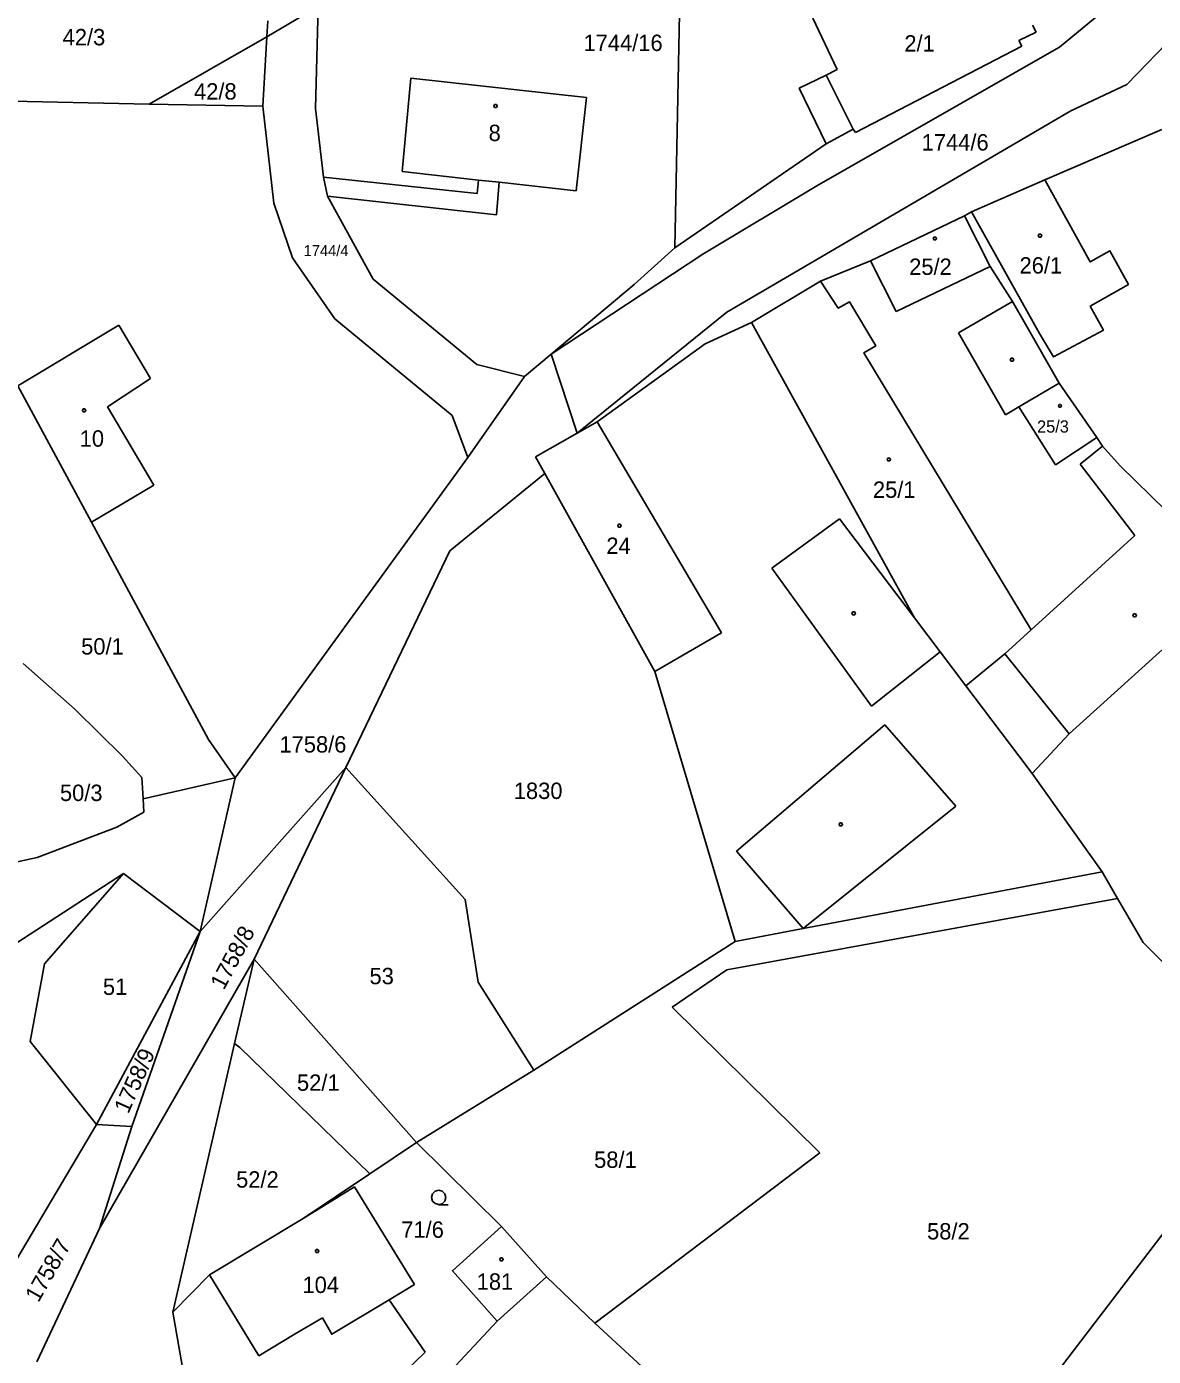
# Model space of a CAD drawing. Extents: x -799786 to -795190, y -1021716 to -1017834.
# Drawn here: x -798047.9 to -797930.9, y -1019191.9 to -1019053.9 of the extents above; entities that cross this region are included whole.
import ezdxf

# ---------------------------------------------------------------- set-up
doc = ezdxf.new("R2010")
doc.units = 0
for name, color, linetype in [('Default', 7, 'Continuous'), ('KN_HRANICE', 7, 'Continuous'), ('KN_KULTURY', 7, 'Continuous'), ('KN_PARCELY', 7, 'Continuous'), ('KN_SLUCKY', 7, 'Continuous')]:
    doc.layers.add(name, color=color, linetype=linetype)

# ---------------------------------------------------------------- blocks, each defined once
blk = doc.blocks.new('304')
at = {"layer": 'Default'}
blk.add_lwpolyline([(0, 0), (-0.38, 0.1), (-0.65, 0.37), (-0.75, 0.74), (-0.65, 1.11), (-0.38, 1.38), (-0.01, 1.48), (0.36, 1.38), (0.63, 1.11), (0.73, 0.73), (0.63, 0.35), (0.36, 0.08), (-0.02, -0.02), (0.98, -0.02)], dxfattribs=at)
blk = doc.blocks.new('NAHRADNI_SYMBOL')
at = {"layer": 'Default'}
blk.add_lwpolyline([(0.09, 0.15), (0.18, 0), (0.09, -0.15), (-0.09, -0.15), (-0.18, 0), (-0.09, 0.15), (0.09, 0.15)], dxfattribs=at)
blk = doc.blocks.new('402')
at = {"layer": 'Default'}
blk.add_lwpolyline([(0.09, 0.15), (0.18, 0), (0.09, -0.15), (-0.09, -0.15), (-0.18, 0), (-0.09, 0.15), (0.09, 0.15)], dxfattribs=at)

msp = doc.modelspace()

# ---------------------------------------------------------------- linework, layer by layer
at = {"layer": 'KN_HRANICE'}
for p, q in [((-797979.99, -1019047.61), (-797980.56, -1019076.83)), ((-797934.54, -1019050.94), (-797940.64, -1019055.99)), ((-798022.92, -1019054.93), (-798017.6, -1019051.79)), ((-798017.6, -1019051.79), (-798017.86, -1019062.37)), ((-797966.24, -1019053), (-797963.7, -1019058.32)), ((-798022.83, -1019053.26), (-798022.92, -1019054.93)), ((-797944.84, -1019055.3), (-797943.07, -1019054.43)), ((-797943.44, -1019053.71), (-797943.07, -1019054.43)), ((-798035.14, -1019061.9), (-798022.92, -1019054.93)), ((-798022.92, -1019054.93), (-798023.33, -1019062.14)), ((-797944.53, -1019055.88), (-797944.84, -1019055.3)), ((-797933.64, -1019059.89), (-797928.48, -1019054.53)), ((-797940.64, -1019055.99), (-797965.65, -1019070.29)), ((-797961.81, -1019064.86), (-797944.53, -1019055.88)), ((-797964.86, -1019058.91), (-797963.7, -1019058.32)), ((-798008.89, -1019068.91), (-798007.98, -1019059.22)), ((-798007.98, -1019059.22), (-797989.73, -1019061.24)), ((-797967.67, -1019060.26), (-797964.86, -1019058.91)), ((-797939.47, -1019062.61), (-797933.64, -1019059.89)), ((-797989.73, -1019061.24), (-797990.8, -1019070.91)), ((-797964.85, -1019066.02), (-797967.67, -1019060.26)), ((-798035.14, -1019061.9), (-798051.33, -1019061.57)), ((-798023.33, -1019062.14), (-798035.14, -1019061.9)), ((-798023.33, -1019062.14), (-798022.2, -1019072.21)), ((-798017.86, -1019062.37), (-798017.06, -1019069.5)), ((-797975.16, -1019083.51), (-797939.47, -1019062.61)), ((-797964.85, -1019066.02), (-797962.04, -1019064.5)), ((-797962.04, -1019064.5), (-797961.81, -1019064.86)), ((-797942.17, -1019069.78), (-797930, -1019064.56)), ((-797980.56, -1019076.83), (-797964.85, -1019066.02)), ((-798017.06, -1019069.5), (-798016.63, -1019071.48)), ((-798001.09, -1019071.18), (-798017.06, -1019069.5)), ((-798000.94, -1019069.79), (-798008.89, -1019068.91)), ((-798000.94, -1019069.79), (-798001.09, -1019071.18)), ((-797998.8, -1019070.03), (-797999.09, -1019073.4)), ((-797990.8, -1019070.91), (-797998.8, -1019070.03)), ((-797965.65, -1019070.29), (-797977.66, -1019077.48)), ((-797949.77, -1019073.09), (-797942.17, -1019069.78)), ((-798022.2, -1019072.21), (-798020.28, -1019077.86)), ((-798016.63, -1019071.48), (-798011.89, -1019080.08)), ((-798016.63, -1019071.48), (-797999.09, -1019073.4)), ((-797960.26, -1019078.18), (-797950.51, -1019073.52)), ((-797950.51, -1019073.52), (-797949.77, -1019073.09)), ((-797947.83, -1019078.78), (-797950.51, -1019073.52)), ((-798020.28, -1019077.86), (-798015.86, -1019084.19)), ((-797977.66, -1019077.48), (-797993.4, -1019087.85)), ((-797984.78, -1019080.65), (-797980.56, -1019076.83)), ((-797965.46, -1019080.28), (-797960.26, -1019078.18)), ((-797957.58, -1019083.44), (-797960.26, -1019078.18)), ((-797957.58, -1019083.44), (-797947.83, -1019078.78)), ((-797947.83, -1019078.78), (-797945.52, -1019082.39)), ((-798011.89, -1019080.08), (-798001.14, -1019088.93)), ((-797993.4, -1019087.85), (-797984.78, -1019080.65)), ((-797972.6, -1019084.58), (-797965.46, -1019080.28)), ((-797945.52, -1019082.39), (-797944.16, -1019084.77)), ((-798015.86, -1019084.19), (-798003.7, -1019094.22)), ((-797975.16, -1019083.51), (-797990.71, -1019096.07)), ((-797977.41, -1019086.81), (-797972.6, -1019084.58)), ((-797972.6, -1019084.58), (-797955.69, -1019115.25)), ((-797944.16, -1019084.77), (-797940.66, -1019090.89)), ((-797988.62, -1019094.88), (-797977.41, -1019086.81)), ((-798001.14, -1019088.93), (-797996.19, -1019090.18)), ((-797996.19, -1019090.18), (-797993.4, -1019087.85)), ((-797993.4, -1019087.85), (-797990.71, -1019096.07)), ((-798002.07, -1019098.6), (-797996.19, -1019090.18)), ((-798041.14, -1019105.32), (-798048.79, -1019091.15)), ((-797944.86, -1019093.34), (-797940.66, -1019090.89)), ((-797940.66, -1019090.89), (-797936.77, -1019096.53)), ((-798003.7, -1019094.22), (-798002.07, -1019098.6)), ((-797944.86, -1019093.34), (-797941.05, -1019099.35)), ((-797990.71, -1019096.07), (-797988.62, -1019094.88)), ((-797995.05, -1019098.54), (-797990.71, -1019096.07)), ((-797941.05, -1019099.35), (-797936.77, -1019096.53)), ((-797936.77, -1019096.53), (-797936.16, -1019097.42)), ((-798002.07, -1019098.6), (-798026.22, -1019131.83)), ((-797995.05, -1019098.54), (-797994.08, -1019100.27)), ((-797936.16, -1019097.42), (-797934.34, -1019099.45)), ((-797934.34, -1019099.45), (-797929.59, -1019104.1)), ((-797994.08, -1019100.27), (-798003.92, -1019108.28)), ((-797994.08, -1019100.27), (-797982.65, -1019120.79)), ((-798028.98, -1019127.85), (-798041.14, -1019105.32)), ((-798003.92, -1019108.28), (-798014.72, -1019130.78)), ((-797939.64, -1019127.27), (-797922.11, -1019111.42)), ((-797953.02, -1019118.78), (-797955.69, -1019115.25)), ((-797950.37, -1019122.28), (-797953.02, -1019118.78)), ((-798048.24, -1019119.97), (-798042.83, -1019124.75)), ((-797982.65, -1019120.79), (-797974.31, -1019148.84)), ((-797944.86, -1019129.55), (-797950.37, -1019122.28)), ((-798042.83, -1019124.75), (-798037.9, -1019129.58)), ((-797943.46, -1019131.4), (-797939.64, -1019127.27)), ((-798026.22, -1019131.83), (-798028.98, -1019127.85)), ((-798037.9, -1019129.58), (-798035.91, -1019131.81)), ((-797943.46, -1019131.4), (-797944.86, -1019129.55)), ((-798014.72, -1019130.78), (-798029.85, -1019147.81)), ((-798014.72, -1019130.78), (-798024.25, -1019150.65)), ((-798002.35, -1019144.46), (-798014.72, -1019130.78)), ((-797943.46, -1019131.4), (-797936.21, -1019141.61)), ((-798035.91, -1019131.81), (-798035.77, -1019134.03)), ((-798035.77, -1019134.03), (-798026.22, -1019131.83)), ((-798026.22, -1019131.83), (-798029.85, -1019147.81)), ((-798035.77, -1019134.03), (-798035.69, -1019135.42)), ((-798035.69, -1019135.42), (-798038.5, -1019136.97)), ((-798038.5, -1019136.97), (-798046.79, -1019140.13)), ((-798046.79, -1019140.13), (-798049.66, -1019140.75)), ((-798037.82, -1019141.78), (-798057.09, -1019154.27)), ((-798037.82, -1019141.78), (-798046, -1019151.14)), ((-798029.85, -1019147.81), (-798037.82, -1019141.78)), ((-797961.9, -1019146.49), (-797936.21, -1019141.61)), ((-797936.21, -1019141.61), (-797934.6, -1019144.37)), ((-798000.98, -1019153.06), (-798002.35, -1019144.46)), ((-797975.17, -1019151.78), (-797934.6, -1019144.37)), ((-797934.6, -1019144.37), (-797931.93, -1019148.94)), ((-797967.24, -1019147.5), (-797961.9, -1019146.49)), ((-798040.62, -1019167.84), (-798029.85, -1019147.81)), ((-798029.85, -1019147.81), (-798036.96, -1019168.05)), ((-797974.31, -1019148.84), (-797967.24, -1019147.5)), ((-797995.22, -1019162.2), (-797974.31, -1019148.84)), ((-797931.93, -1019148.94), (-797917.67, -1019163.19)), ((-798040.29, -1019178.61), (-798024.25, -1019150.65)), ((-798024.25, -1019150.65), (-798026.27, -1019159.43)), ((-798024.25, -1019150.65), (-798007.38, -1019169.71)), ((-798046, -1019151.14), (-798047.51, -1019159.22)), ((-797980.83, -1019155.66), (-797975.17, -1019151.78)), ((-798000.98, -1019153.06), (-797995.22, -1019162.2)), ((-797965.53, -1019170.76), (-797980.83, -1019155.66)), ((-798047.51, -1019159.22), (-798040.62, -1019167.84)), ((-798026.27, -1019159.43), (-798032.69, -1019187.31)), ((-798025.74, -1019159.83), (-798026.27, -1019159.43)), ((-798012.22, -1019172.95), (-798025.74, -1019159.83)), ((-798007.38, -1019169.71), (-797995.22, -1019162.2)), ((-797958.45, -1019216.47), (-797917.67, -1019163.19)), ((-798053.76, -1019189.97), (-798040.62, -1019167.84)), ((-798040.62, -1019167.84), (-798036.96, -1019168.05)), ((-798036.96, -1019168.05), (-798040.29, -1019178.61)), ((-798012.22, -1019172.95), (-798007.38, -1019169.71)), ((-797998.56, -1019178.4), (-798007.38, -1019169.71)), ((-797988.89, -1019188.44), (-797965.53, -1019170.76)), ((-798019.17, -1019177.58), (-798012.22, -1019172.95)), ((-798019.17, -1019177.58), (-798013.83, -1019174.29)), ((-798013.83, -1019174.29), (-798007.6, -1019184.43)), ((-798046.82, -1019192.47), (-798040.29, -1019178.61)), ((-798028.89, -1019183.42), (-798019.17, -1019177.58)), ((-797993.89, -1019183.63), (-797998.56, -1019178.4)), ((-798028.89, -1019183.42), (-798032.69, -1019187.31)), ((-797993.89, -1019183.63), (-797999, -1019188.24)), ((-797988.89, -1019188.44), (-797993.89, -1019183.63)), ((-798010.23, -1019186.02), (-798007.6, -1019184.43)), ((-798006.49, -1019191.45), (-798010.23, -1019186.02)), ((-798032.69, -1019187.31), (-798030.99, -1019196.93)), ((-797999, -1019188.24), (-798004.3, -1019193.91)), ((-797958.45, -1019216.47), (-797988.89, -1019188.44)), ((-798008.6, -1019193.51), (-798006.49, -1019191.45))]:
    msp.add_line(p, q, dxfattribs=at)
msp.add_lwpolyline([(-797998.56, -1019178.4), (-798003.67, -1019183.01), (-797999, -1019188.24)], dxfattribs=at)
at = {"layer": 'KN_SLUCKY'}
for p, q in [((-797964.86, -1019058.91), (-797962.04, -1019064.5)), ((-797998.8, -1019070.03), (-798000.94, -1019069.79)), ((-797945.52, -1019082.39), (-797951.1, -1019085.66)), ((-798048.79, -1019091.15), (-798038.3, -1019084.86)), ((-798038.3, -1019084.86), (-798035.02, -1019090.4)), ((-797951.1, -1019085.66), (-797946.24, -1019094.15)), ((-798035.02, -1019090.4), (-798039.46, -1019093.32)), ((-798039.46, -1019093.32), (-798034.65, -1019101.48)), ((-797946.24, -1019094.15), (-797944.86, -1019093.34)), ((-797988.62, -1019094.88), (-797975.73, -1019116.8)), ((-797936.16, -1019097.42), (-797938.48, -1019099.3)), ((-797938.48, -1019099.3), (-797932.82, -1019106.7)), ((-798034.65, -1019101.48), (-798041.14, -1019105.32)), ((-797970.49, -1019110.09), (-797963.48, -1019104.97)), ((-797955.69, -1019115.25), (-797963.48, -1019104.97)), ((-797932.82, -1019106.7), (-797943.58, -1019116.49)), ((-797970.49, -1019110.09), (-797960.15, -1019124.4)), ((-797943.58, -1019116.49), (-797946.31, -1019118.97)), ((-797975.73, -1019116.8), (-797982.65, -1019120.79)), ((-797960.15, -1019124.4), (-797953.02, -1019118.78)), ((-797950.37, -1019122.28), (-797946.31, -1019118.97)), ((-797946.31, -1019118.97), (-797939.64, -1019127.27)), ((-797974.16, -1019139.45), (-797958.75, -1019126.34)), ((-797958.75, -1019126.34), (-797951.38, -1019134.78)), ((-797967.24, -1019147.5), (-797951.38, -1019134.78)), ((-797967.24, -1019147.5), (-797974.16, -1019139.45)), ((-798028.89, -1019183.42), (-798023.76, -1019191.83)), ((-798019.98, -1019189.57), (-798017.14, -1019187.88)), ((-798023.76, -1019191.83), (-798019.98, -1019189.57))]:
    msp.add_line(p, q, dxfattribs=at)
for points in [[(-797942.17, -1019069.78), (-797937.43, -1019078.29), (-797935.39, -1019077.15), (-797933.47, -1019080.62), (-797937.43, -1019082.88), (-797936.07, -1019085.37), (-797941.25, -1019088.16), (-797942.71, -1019085.73), (-797949.77, -1019073.09)], [(-797943.58, -1019116.49), (-797960.93, -1019087.72), (-797959.71, -1019087.01), (-797962.45, -1019082.43), (-797963.61, -1019083.09), (-797965.46, -1019080.28)], [(-798017.14, -1019187.88), (-798016.19, -1019189.6), (-798010.23, -1019186.02)]]:
    msp.add_lwpolyline(points, dxfattribs=at)

# ---------------------------------------------------------------- block references
at = {"layer": 'KN_KULTURY'}
for name, p in [('402', (-797999.19, -1019062.11)), ('402', (-797953.57, -1019075.86)), ('402', (-797942.66, -1019075.56)), ('402', (-797945.56, -1019088.44)), ('NAHRADNI_SYMBOL', (-798041.9, -1019093.7)), ('402', (-797958.35, -1019098.8)), ('402', (-797986.32, -1019105.68)), ('402', (-797962, -1019114.78)), ('402', (-797932.83, -1019114.98)), ('402', (-797963.34, -1019136.68)), ('304', (-798005.07, -1019176.14)), ('402', (-798017.71, -1019180.97)), ('402', (-797998.57, -1019181.83))]:
    msp.add_blockref(name, p, dxfattribs=at)
at = {"layer": 'KN_KULTURY', "xscale": 0.89, "yscale": 0.89}
msp.add_blockref('402', (-797940.59, -1019093.23), dxfattribs=at)

# ---------------------------------------------------------------- texts
at = {"layer": 'KN_PARCELY'}
for s, height, p in [('42/3', 1.7, (-798044.13, -1019055.81)), ('1744/16', 1.7, (-797990.05, -1019056.4)), ('2/1', 1.7, (-797956.74, -1019056.46)), ('42/8', 1.7, (-798030.49, -1019061.44)), ('8', 1.7, (-797999.9, -1019065.75)), ('1744/6', 1.7, (-797954.94, -1019066.73)), ('1744/4', 1.14, (-798019.11, -1019077.69)), ('25/2', 1.7, (-797956.24, -1019079.64)), ('26/1', 1.7, (-797944.78, -1019079.5)), ('10', 1.7, (-798042.36, -1019097.47)), ('25/1', 1.7, (-797960, -1019102.78)), ('24', 1.7, (-797987.68, -1019108.6)), ('50/1', 1.7, (-798042.21, -1019119.05)), ('1758/6', 1.7, (-798021.62, -1019129.22)), ('50/3', 1.7, (-798044.41, -1019134.25)), ('1830', 1.7, (-797997.29, -1019134.04)), ('53', 1.7, (-798012.27, -1019153.27)), ('51', 1.7, (-798039.95, -1019154.38)), ('52/1', 1.7, (-798019.8, -1019164.33)), ('58/1', 1.7, (-797988.95, -1019172.33)), ('52/2', 1.7, (-798026.12, -1019174.38)), ('71/6', 1.7, (-798008.97, -1019179.59)), ('58/2', 1.7, (-797954.38, -1019179.76)), ('104', 1.7, (-798019.23, -1019185.32)), ('181', 1.7, (-798001.14, -1019184.98))]:
    msp.add_text(s, height=height, dxfattribs=at).set_placement(p)
for s, height, rotation, p in [('25/3', 1.27, 0.286, (-797942.96, -1019096.02)), ('1758/8', 1.7, 61.937, (-798027.39, -1019153.95)), ('1758/9', 1.7, 66.062, (-798037.31, -1019166.79)), ('1758/7', 1.7, 60.39, (-798046.64, -1019186.38))]:
    msp.add_text(s, height=height, rotation=rotation, dxfattribs=at).set_placement(p)

doc.saveas('drawing.dxf')
